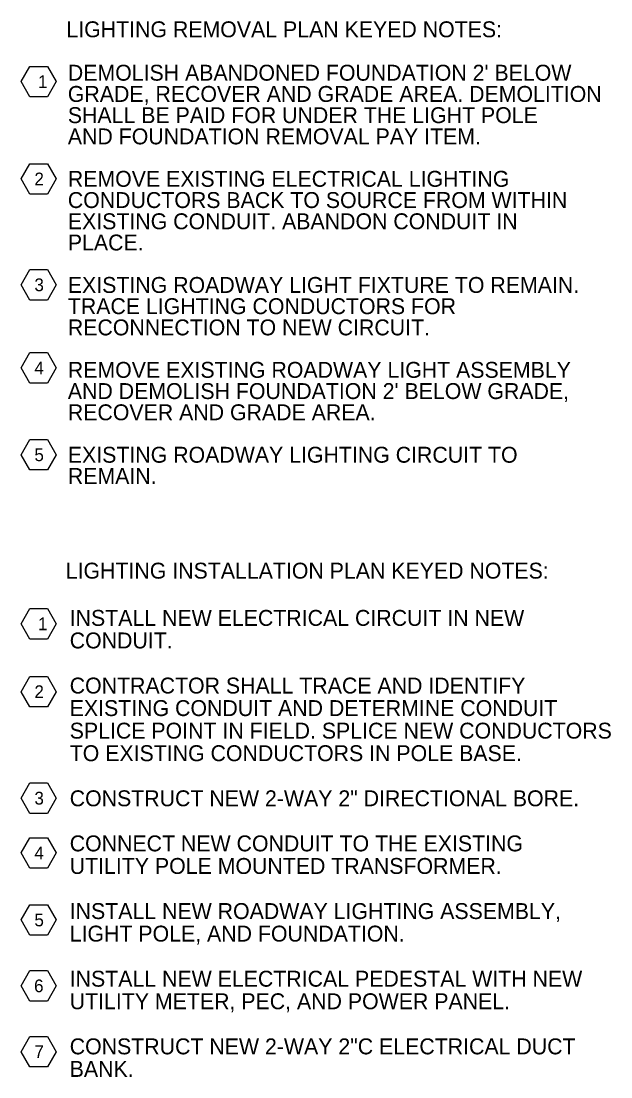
# Model space of a CAD drawing. Extents: x -3.65 to 4.44, y 0.05 to 1.76.
# Drawn here: x -0.473 to -0.103, y 0.596 to 1.26 of the extents above; entities that cross this region are included whole.
import ezdxf

# ---------------------------------------------------------------- set-up
doc = ezdxf.new("R2010")
doc.units = 0
for name, color, linetype in [('E-ANNO-KEYN', 7, 'Continuous'), ('E-ANNO-NOTE', 7, 'Continuous'), ('E-ANNO-TEXT', 7, 'Continuous')]:
    doc.layers.add(name, color=color, linetype=linetype)

msp = doc.modelspace()

# ---------------------------------------------------------------- linework, layer by layer
at = {"layer": 'E-ANNO-KEYN'}
for points in [[(-0.4569, 1.23167), (-0.45137, 1.22209), (-0.4569, 1.21251), (-0.46796, 1.21251), (-0.47349, 1.22209), (-0.46796, 1.23167)], [(-0.4569, 1.17041), (-0.45137, 1.16083), (-0.4569, 1.15125), (-0.46796, 1.15125), (-0.47349, 1.16083), (-0.46796, 1.17041)], [(-0.4569, 1.1038), (-0.45137, 1.09422), (-0.4569, 1.08464), (-0.46796, 1.08464), (-0.47349, 1.09422), (-0.46796, 1.1038)], [(-0.4569, 1.0515), (-0.45137, 1.04192), (-0.4569, 1.03234), (-0.46796, 1.03234), (-0.47349, 1.04192), (-0.46796, 1.0515)], [(-0.4569, 0.99681), (-0.45137, 0.98723), (-0.4569, 0.97765), (-0.46796, 0.97765), (-0.47349, 0.98723), (-0.46796, 0.99681)], [(-0.4569, 0.8904), (-0.45137, 0.88082), (-0.4569, 0.87124), (-0.46796, 0.87124), (-0.47349, 0.88082), (-0.46796, 0.8904)], [(-0.4569, 0.84766), (-0.45137, 0.83808), (-0.4569, 0.8285), (-0.46796, 0.8285), (-0.47349, 0.83808), (-0.46796, 0.84766)], [(-0.4569, 0.78065), (-0.45137, 0.77107), (-0.4569, 0.76149), (-0.46796, 0.76149), (-0.47349, 0.77107), (-0.46796, 0.78065)], [(-0.4569, 0.7462), (-0.45137, 0.73662), (-0.4569, 0.72704), (-0.46796, 0.72704), (-0.47349, 0.73662), (-0.46796, 0.7462)], [(-0.4569, 0.70397), (-0.45137, 0.69439), (-0.4569, 0.68481), (-0.46796, 0.68481), (-0.47349, 0.69439), (-0.46796, 0.70397)], [(-0.4569, 0.66251), (-0.45137, 0.65293), (-0.4569, 0.64335), (-0.46796, 0.64335), (-0.47349, 0.65293), (-0.46796, 0.66251)], [(-0.4569, 0.62105), (-0.45137, 0.61147), (-0.4569, 0.60189), (-0.46796, 0.60189), (-0.47349, 0.61147), (-0.46796, 0.62105)]]:
    msp.add_lwpolyline(points, close=True, dxfattribs=at)

# ---------------------------------------------------------------- texts
at = {"layer": 'E-ANNO-NOTE'}
for s, rotation, p in [('LIGHTING REMOVAL PLAN KEYED NOTES:', 0.00005, (-0.44502, 1.25002)), ("DEMOLISH ABANDONED FOUNDATION 2' BELOW ", 360, (-0.44412, 1.2227)), ('GRADE, RECOVER AND GRADE AREA. DEMOLITION ', 360, (-0.44412, 1.20934)), ('SHALL BE PAID FOR UNDER THE LIGHT POLE ', 360, (-0.44412, 1.19598)), ('AND FOUNDATION REMOVAL PAY ITEM.', 360, (-0.44412, 1.18262)), ('REMOVE EXISTING ELECTRICAL LIGHTING ', 360, (-0.44412, 1.1559)), ('CONDUCTORS BACK TO SOURCE FROM WITHIN ', 360, (-0.44412, 1.14254)), ('EXISTING CONDUIT. ABANDON CONDUIT IN ', 360, (-0.44412, 1.12918)), ('PLACE.', 360, (-0.44412, 1.11582)), ('EXISTING ROADWAY LIGHT FIXTURE TO REMAIN. ', 360, (-0.44412, 1.0891)), ('TRACE LIGHTING CONDUCTORS FOR ', 360, (-0.44412, 1.07574)), ('RECONNECTION TO NEW CIRCUIT.', 360, (-0.44412, 1.06238)), ('REMOVE EXISTING ROADWAY LIGHT ASSEMBLY ', 360, (-0.44412, 1.03566)), ("AND DEMOLISH FOUNDATION 2' BELOW GRADE, ", 360, (-0.44412, 1.0223)), ('RECOVER AND GRADE AREA.', 360, (-0.44412, 1.00894)), ('EXISTING ROADWAY LIGHTING CIRCUIT TO ', 360, (-0.44412, 0.98222)), ('REMAIN.', 360, (-0.44412, 0.96886)), ('LIGHTING INSTALLATION PLAN KEYED NOTES:', 0.00005, (-0.44543, 0.90926)), ('INSTALL NEW ELECTRICAL CIRCUIT IN NEW ', 360, (-0.44294, 0.87953)), ('CONDUIT.', 360, (-0.44294, 0.86533)), ('CONTRACTOR SHALL TRACE AND IDENTIFY ', 360, (-0.44294, 0.83694)), ('EXISTING CONDUIT AND DETERMINE CONDUIT ', 360, (-0.44294, 0.82275)), ('SPLICE POINT IN FIELD. SPLICE NEW CONDUCTORS ', 360, (-0.44294, 0.80855)), ('TO EXISTING CONDUCTORS IN POLE BASE.', 360, (-0.44294, 0.79436)), ('CONSTRUCT NEW 2-WAY 2" DIRECTIONAL BORE.', 360, (-0.44294, 0.76597)), ('CONNECT NEW CONDUIT TO THE EXISTING ', 360, (-0.44294, 0.73758)), ('UTILITY POLE MOUNTED TRANSFORMER.', 360, (-0.44294, 0.72338)), ('INSTALL NEW ROADWAY LIGHTING ASSEMBLY, ', 360, (-0.44294, 0.69499)), ('LIGHT POLE, AND FOUNDATION.', 360, (-0.44294, 0.6808)), ('INSTALL NEW ELECTRICAL PEDESTAL WITH NEW ', 360, (-0.44294, 0.65241)), ('UTILITY METER, PEC, AND POWER PANEL.', 360, (-0.44294, 0.63821)), ('CONSTRUCT NEW 2-WAY 2"C ELECTRICAL DUCT ', 360, (-0.44294, 0.60982)), ('BANK.', 360, (-0.44294, 0.59563))]:
    msp.add_text(s, height=0.01002, rotation=rotation, dxfattribs=at).set_placement(p)
at = {"layer": 'E-ANNO-TEXT'}
for s, p in [('1', (-0.46287, 1.21808)), ('2', (-0.46514, 1.15682)), ('3', (-0.46514, 1.09021)), ('4', (-0.46514, 1.03791)), ('5', (-0.46514, 0.98322)), ('1', (-0.46287, 0.87681)), ('2', (-0.46514, 0.83407)), ('3', (-0.46514, 0.76706)), ('4', (-0.46514, 0.73261)), ('5', (-0.46514, 0.69039)), ('6', (-0.46536, 0.64892)), ('7', (-0.46514, 0.60746))]:
    msp.add_text(s, height=0.00802, rotation=0, dxfattribs=at).set_placement(p)

doc.saveas('drawing.dxf')
